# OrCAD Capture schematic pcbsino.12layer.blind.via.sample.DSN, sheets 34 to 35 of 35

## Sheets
34 Pg33: Expansion Connector: size C
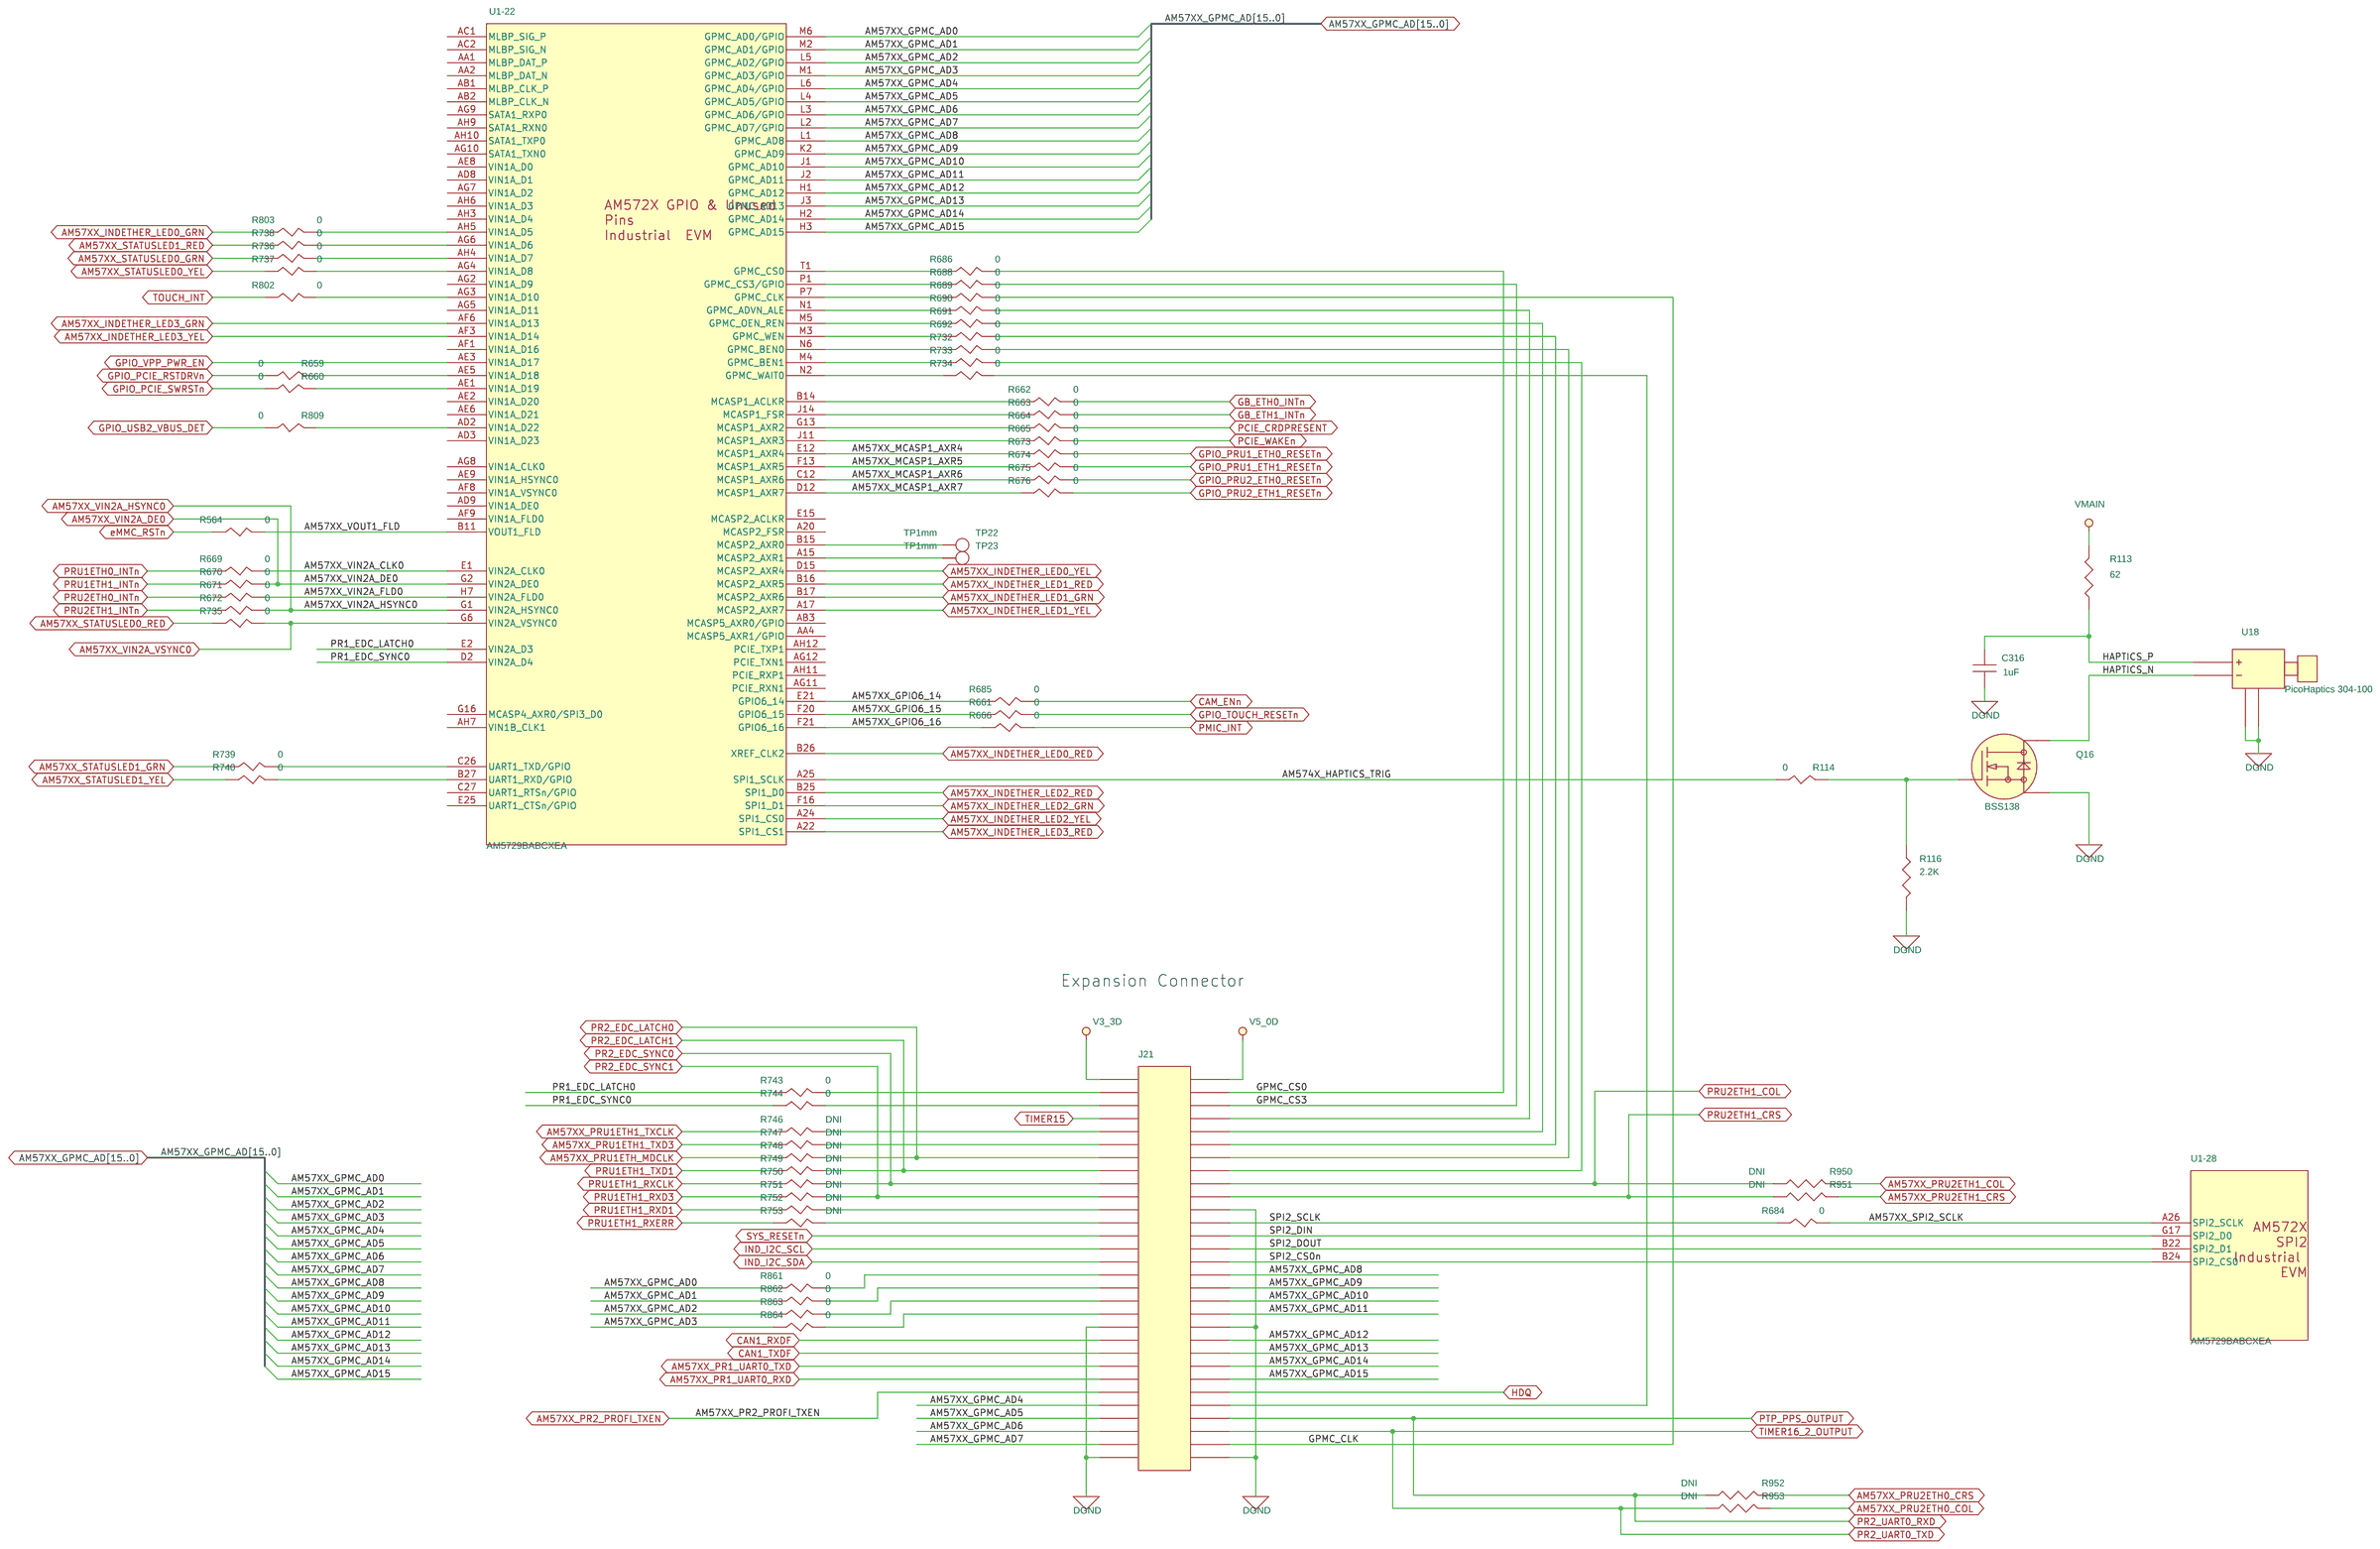
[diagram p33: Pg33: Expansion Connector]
35 Pg15: Ind Ethrnt & Status LED's: size C
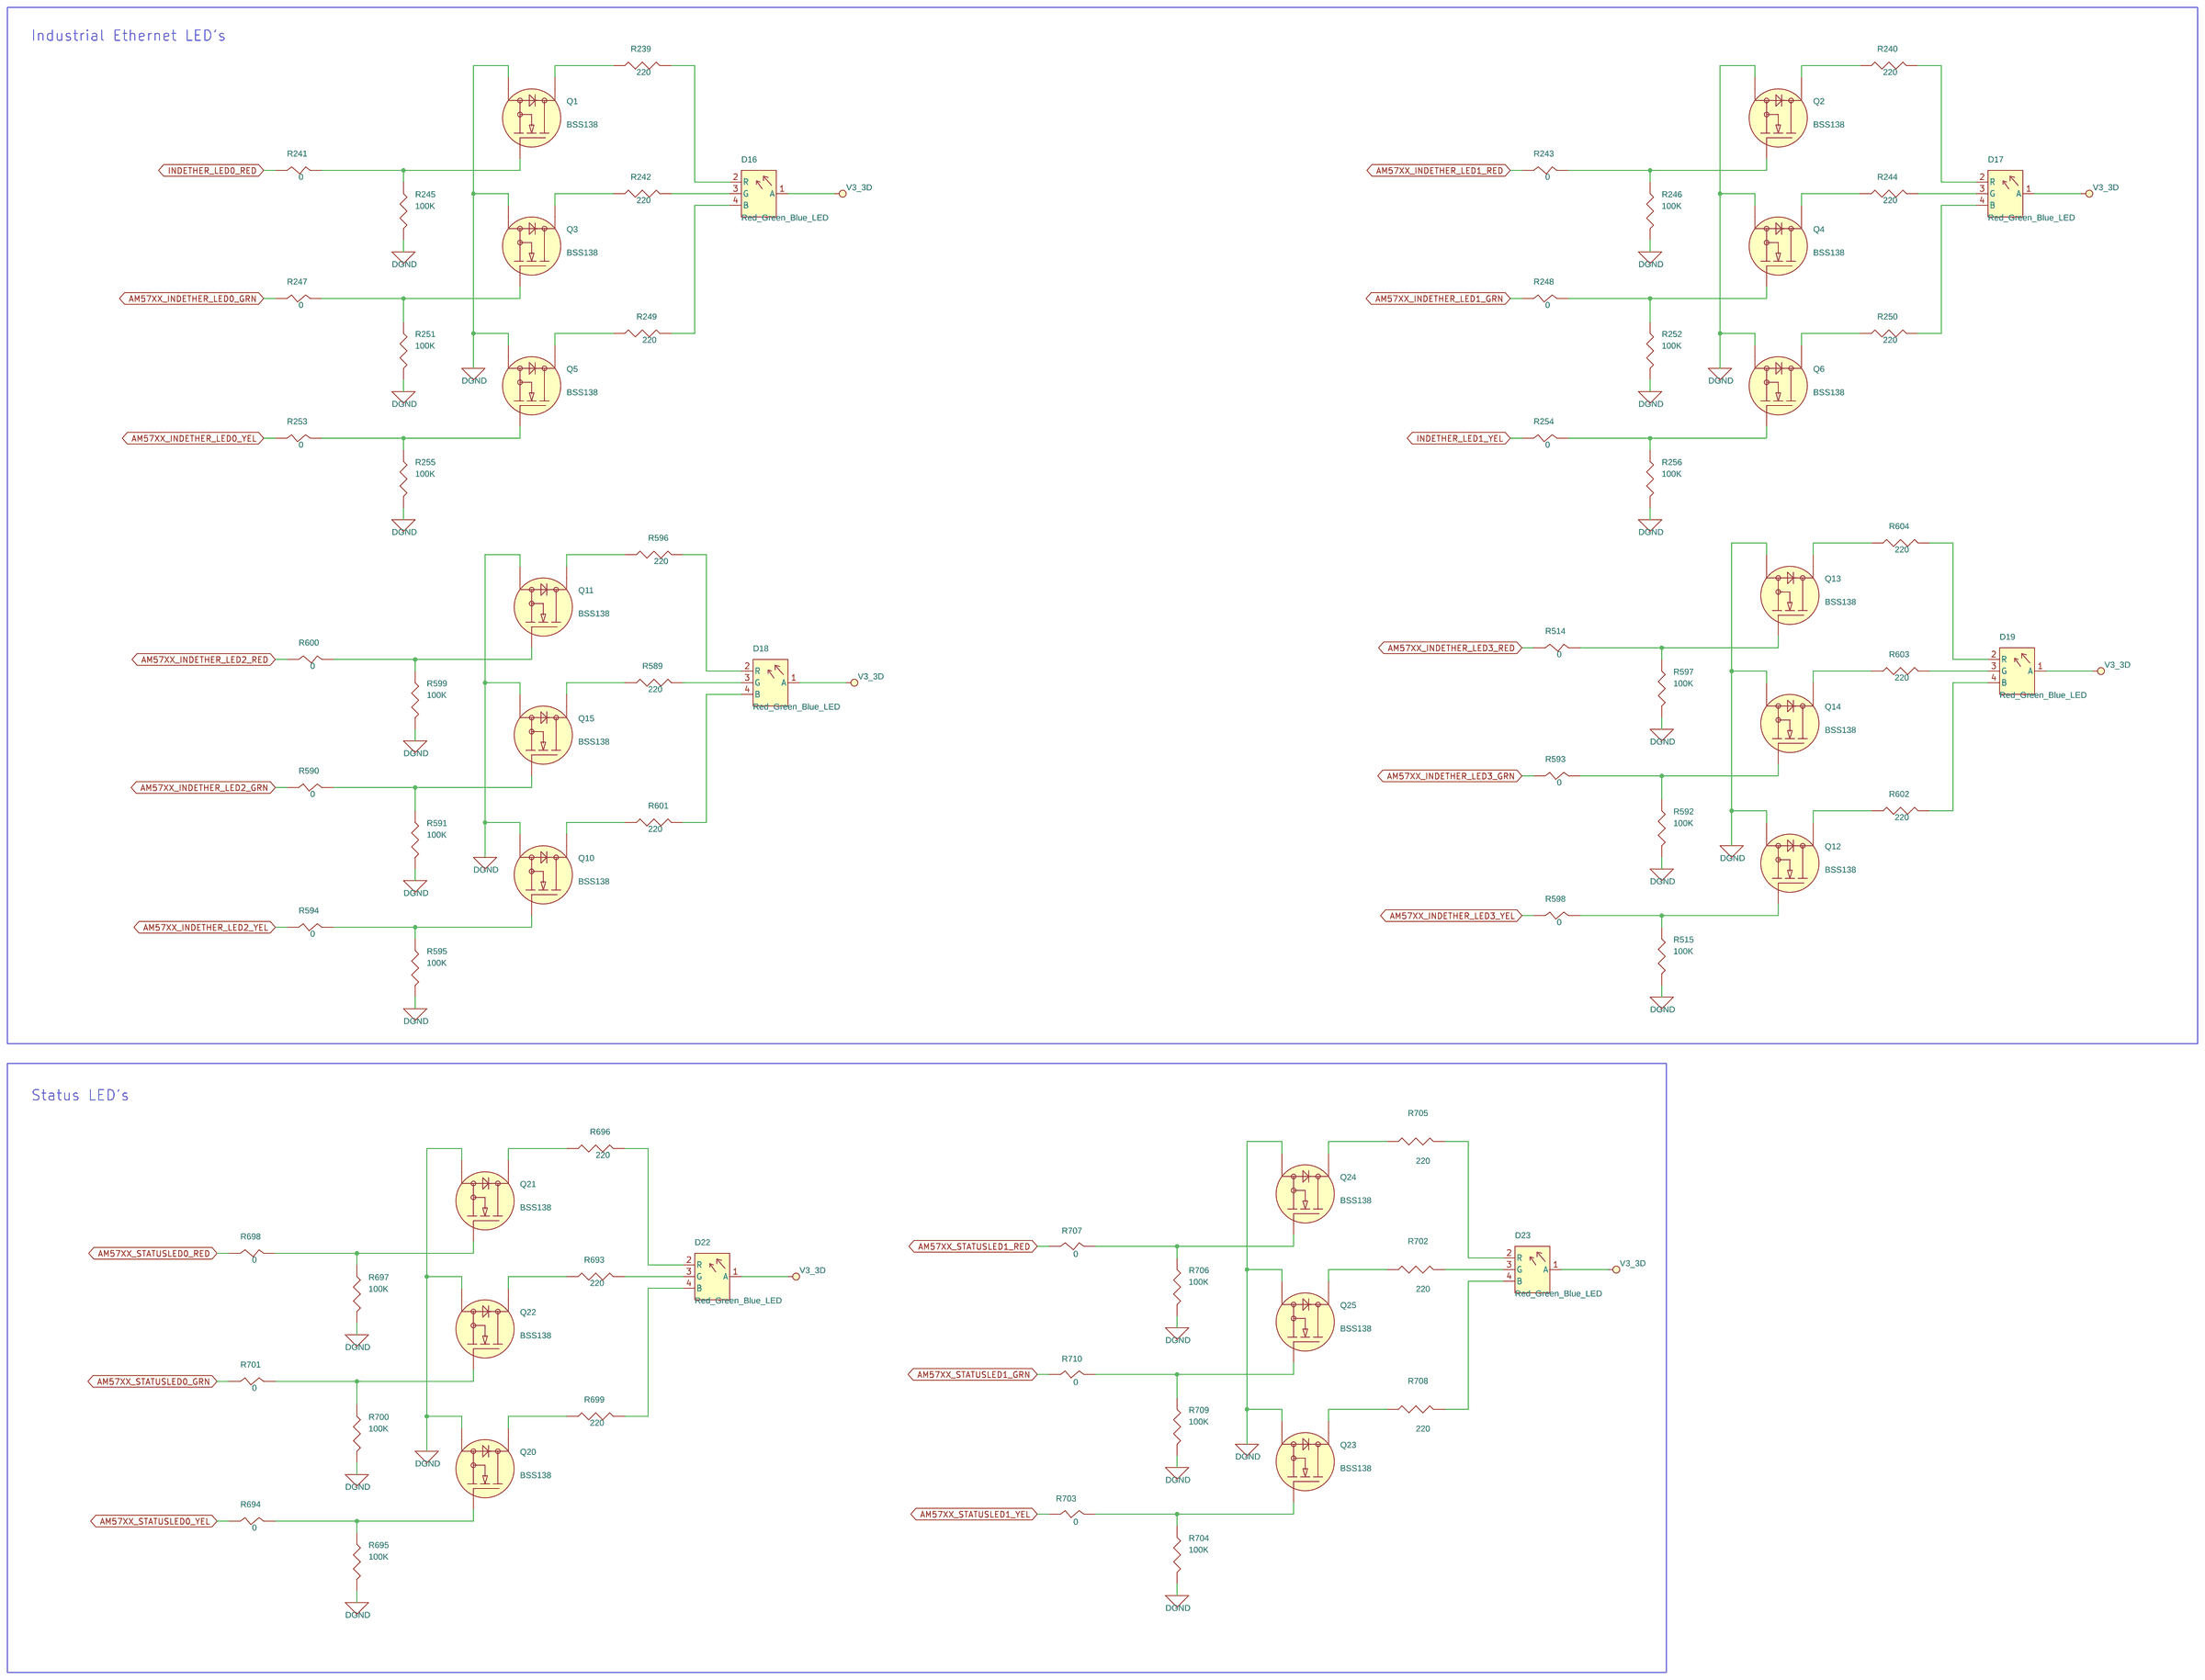
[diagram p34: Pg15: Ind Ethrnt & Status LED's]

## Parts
sheet Pg15: Ind Ethrnt & Status LED's
D16  Red_Green_Blue_LED  [LED-SM1210]
D17  Red_Green_Blue_LED  [LED-SM1210]
D18  Red_Green_Blue_LED  [LED-SM1210]
D19  Red_Green_Blue_LED  [LED-SM1210]
D22  Red_Green_Blue_LED  [LED-SM1210]
D23  Red_Green_Blue_LED  [LED-SM1210]
Q1  BSS138  [SOT23-3]
Q2  BSS138  [SOT23-3]
Q3  BSS138  [SOT23-3]
Q4  BSS138  [SOT23-3]
Q5  BSS138  [SOT23-3]
Q6  BSS138  [SOT23-3]
Q10  BSS138  [SOT23-3]
Q11  BSS138  [SOT23-3]
Q12  BSS138  [SOT23-3]
Q13  BSS138  [SOT23-3]
Q14  BSS138  [SOT23-3]
Q15  BSS138  [SOT23-3]
Q20  BSS138  [SOT23-3]
Q21  BSS138  [SOT23-3]
Q22  BSS138  [SOT23-3]
Q23  BSS138  [SOT23-3]
Q24  BSS138  [SOT23-3]
Q25  BSS138  [SOT23-3]
R239  220  [SM-7351-RES-0402]
R240  220  [SM-7351-RES-0402]
R241  0  [SM-7351-RES-0402]
R242  220  [SM-7351-RES-0402]
R243  0  [SM-7351-RES-0402]
R244  220  [SM-7351-RES-0402]
R245  100K  [SM-7351-RES-0402]
R246  100K  [SM-7351-RES-0402]
R247  0  [SM-7351-RES-0402]
R248  0  [SM-7351-RES-0402]
R249  220  [SM-7351-RES-0402]
R250  220  [SM-7351-RES-0402]
R251  100K  [SM-7351-RES-0402]
R252  100K  [SM-7351-RES-0402]
R253  0  [SM-7351-RES-0402]
R254  0  [SM-7351-RES-0402]
R255  100K  [SM-7351-RES-0402]
R256  100K  [SM-7351-RES-0402]
R514  0  [SM-7351-RES-0402]
R515  100K  [SM-7351-RES-0402]
R589  220  [SM-7351-RES-0402]
R590  0  [SM-7351-RES-0402]
R591  100K  [SM-7351-RES-0402]
R592  100K  [SM-7351-RES-0402]
R593  0  [SM-7351-RES-0402]
R594  0  [SM-7351-RES-0402]
R595  100K  [SM-7351-RES-0402]
R596  220  [SM-7351-RES-0402]
R597  100K  [SM-7351-RES-0402]
R598  0  [SM-7351-RES-0402]
R599  100K  [SM-7351-RES-0402]
R600  0  [SM-7351-RES-0402]
R601  220  [SM-7351-RES-0402]
R602  220  [SM-7351-RES-0402]
R603  220  [SM-7351-RES-0402]
R604  220  [SM-7351-RES-0402]
R693  220  [SM-7351-RES-0402]
R694  0  [SM-7351-RES-0402]
R695  100K  [SM-7351-RES-0402]
R696  220  [SM-7351-RES-0402]
R697  100K  [SM-7351-RES-0402]
R698  0  [SM-7351-RES-0402]
R699  220  [SM-7351-RES-0402]
R700  100K  [SM-7351-RES-0402]
R701  0  [SM-7351-RES-0402]
R702  220  [SM-7351-RES-0402]
R703  0  [SM-7351-RES-0402]
R704  100K  [SM-7351-RES-0402]
R705  220  [SM-7351-RES-0402]
R706  100K  [SM-7351-RES-0402]
R707  0  [SM-7351-RES-0402]
R708  220  [SM-7351-RES-0402]
R709  100K  [SM-7351-RES-0402]
R710  0  [SM-7351-RES-0402]
sheet Pg22: HDMI
U1  AM5729BABCXEA  [BGA23X23-760-117M]  (sections -1,-10,-11,-12,-13,-14,-15,-16,-17,-18,-19,-2,-20,-21,-22,-23,-24,-25,-26,-27,-28,-29,-3,-4,-5,-6,-7,-8,-9)
sheet Pg33: Expansion Connector
C316  1uF  [CC0603]
J21  Header_30x2_Female  [HDR2X30-2mm-177m]
Q16  BSS138  [SOT23-3]
R113  62  [sm-7351-res-0402]
R114  0  [SM-7351-RES-0402]
R116  2.2K  [sm-7351-res-0402]
R564  0  [SM-7351-RES-0402]
R659  0  [SM-7351-RES-0402]
R660  0  [SM-7351-RES-0402]
R661  0  [SM-7351-RES-0402]
R662  0  [SM-7351-RES-0402]
R663  0  [SM-7351-RES-0402]
R664  0  [SM-7351-RES-0402]
R665  0  [SM-7351-RES-0402]
R666  0  [SM-7351-RES-0402]
R669  0  [SM-7351-RES-0402]
R670  0  [SM-7351-RES-0402]
R671  0  [SM-7351-RES-0402]
R672  0  [SM-7351-RES-0402]
R673  0  [SM-7351-RES-0402]
R674  0  [SM-7351-RES-0402]
R675  0  [SM-7351-RES-0402]
R676  0  [SM-7351-RES-0402]
R684  0  [SM-7351-RES-0402]
R685  0  [SM-7351-RES-0402]
R686  0  [SM-7351-RES-0402]
R688  0  [SM-7351-RES-0402]
R689  0  [SM-7351-RES-0402]
R690  0  [SM-7351-RES-0402]
R691  0  [SM-7351-RES-0402]
R692  0  [SM-7351-RES-0402]
R732  0  [SM-7351-RES-0402]
R733  0  [SM-7351-RES-0402]
R734  0  [SM-7351-RES-0402]
R735  0  [SM-7351-RES-0402]
R736  0  [SM-7351-RES-0402]
R737  0  [SM-7351-RES-0402]
R738  0  [SM-7351-RES-0402]
R739  0  [SM-7351-RES-0402]
R740  0  [SM-7351-RES-0402]
R743  0  [SM-7351-RES-0402]
R744  0  [SM-7351-RES-0402]
R746  DNI  [SM-7351-RES-0402]
R747  DNI  [SM-7351-RES-0402]
R748  DNI  [SM-7351-RES-0402]
R749  DNI  [SM-7351-RES-0402]
R750  DNI  [SM-7351-RES-0402]
R751  DNI  [SM-7351-RES-0402]
R752  DNI  [SM-7351-RES-0402]
R753  DNI  [SM-7351-RES-0402]
R802  0  [SM-7351-RES-0402]
R803  0  [SM-7351-RES-0402]
R809  0  [SM-7351-RES-0402]
R861  0  [SM-7351-RES-0402]
R862  0  [SM-7351-RES-0402]
R863  0  [SM-7351-RES-0402]
R864  0  [SM-7351-RES-0402]
R950  DNI  [RC0402]
R951  DNI  [RC0402]
R952  DNI  [RC0402]
R953  DNI  [RC0402]
TP22  TP1mm  [tp_smd1mmcircle]
TP23  TP1mm  [tp_smd1mmcircle]
U18  PicoHaptics 304-100  [pico_304-100]

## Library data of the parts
D16-D19 D22 D23 = SM1210RGB: LED RedGreenBlue Tricolor 20mA  1210 smd; MANUFACTURER: Bivar
Q1-Q6 Q10-Q16 Q20-Q25 = 1Q_MOSFET_NChan_BSS138_0: MANUFACTURER: Diodes Inc.
R239 R240 R242 R244 R249 R250 R589 R596 R601-R604 R693 R696 R699 R702 R705 R708 = 1R_150ohm1_16W1%SMD0402: Resistor 220ohm 1/10W 1% 0402; MANUFACTURER: PANASONIC; MfrNum: ERJ-2RKF2200X; PartName: 220ohm1/10W1%0402; TIIntPartnumber: 1R0176
R114 R241 R243 R247 R248 R253 R254 R514 R564 R590 R593 R594 R598 R600 R659-R666 R669-R676 R684-R686 R688-R692 R694 R698 R701 R703 R707 R710 R732-R740 R743 R744 R746-R753 R802 R803 R809 R861-R864 = 1R_ZeroOhmResistor1_16W0402: Resistor Zero ohm Jumper 0402; MANUFACTURER: PANASONIC
R245 R246 R251 R252 R255 R256 R515 R591 R592 R595 R597 R599 R695 R697 R700 R704 R706 R709 = 1R_100KOhmResistor1_16W0402: Resistor 100Kohm 1/16W 1% 0402; MANUFACTURER: STACKPOLE ELECTRONICS
U1 = AM5729BABCXEA
C316 = CL10A105KB8NNNC
J21 = NPPN302AFCN-RC: Header, Socket, 30x2,  2mm pitch, Female; MANUFACTURER: Sullins
R113 = RMCF0402FT62R0
R116 = 1R_2.2KOhmResistor1_16W0402: MANUFACTURER: VishayDale
R950-R953 = ERJ-2GE0R00X
TP22 TP23 = 2H_Testpoint_SMD1mmCircle: Testpoint SMD 1mm circle pad; MANUFACTURER: N/A
U18 = 1G_Haptics_Pico_0: Haptics Vibrator 3V 15000 RPM; MANUFACTURER: PrecisionMicroDrive

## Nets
DGND: C316.2 J21.22 J21.39 J21.40 J21.59 J21.60 Q1.S(SOURCE) Q2.S(SOURCE) Q3.S(SOURCE) Q4.S(SOURCE) Q5.S(SOURCE) Q6.S(SOURCE) Q10.S(SOURCE) Q11.S(SOURCE) Q12.S(SOURCE) Q13.S(SOURCE) Q14.S(SOURCE) Q15.S(SOURCE) Q16.S(SOURCE) Q20.S(SOURCE) Q21.S(SOURCE) Q22.S(SOURCE) Q23.S(SOURCE) Q24.S(SOURCE) Q25.S(SOURCE) R116.1(P1) R245.1(P1) R246.1(P1) R251.1(P1) R252.1(P1) R255.1(P1) R256.1(P1) R515.1(P1) R591.1(P1) R592.1(P1) R595.1(P1) R597.1(P1) R599.1(P1) R695.1(P1) R697.1(P1) R700.1(P1) R704.1(P1) R706.1(P1) R709.1(P1) U18.M1 U18.M2 ; also on sheet 1 2 3 4 5 6 8 9 11 12 13 14 15 16 17 18 19 20 21 22 23 24 25 26 27 28 29 30 31 32 33
V3_3D: D16.1(A) D17.1(A) D18.1(A) D19.1(A) D22.1(A) D23.1(A) J21.1 ; also on sheet 2 3 4 5 6 8 9 11 12 13 14 15 16 17 18 19 21 22 23 24 25 26 27 28 29 30 31 32 33
V5_0D: J21.2 ; also on sheet 4 14 16 18 21
AM57XX_GPIO6_14: R685.2(P2) U1.E21(GPIO6_14)
AM57XX_GPIO6_15: R661.2(P2) U1.F20(GPIO6_15)
AM57XX_GPIO6_16: R666.2(P2) U1.F21(GPIO6_16)
AM57XX_GPMC_AD0: R861.2(P2) U1.M6(GPMC_AD0/GPIO) ; also on sheet 15
AM57XX_GPMC_AD1: R862.2(P2) U1.M2(GPMC_AD1/GPIO) ; also on sheet 15
AM57XX_GPMC_AD2: R863.2(P2) U1.L5(GPMC_AD2/GPIO) ; also on sheet 15
AM57XX_GPMC_AD3: R864.2(P2) U1.M1(GPMC_AD3/GPIO) ; also on sheet 15
AM57XX_GPMC_AD4: J21.51 U1.L6(GPMC_AD4/GPIO) ; also on sheet 15
AM57XX_GPMC_AD5: J21.53 U1.L4(GPMC_AD5/GPIO) ; also on sheet 15
AM57XX_GPMC_AD6: J21.55 U1.L3(GPMC_AD6/GPIO) ; also on sheet 15
AM57XX_GPMC_AD7: J21.57 U1.L2(GPMC_AD7/GPIO) ; also on sheet 15
AM57XX_GPMC_AD8: J21.32 U1.L1(GPMC_AD8) ; also on sheet 15
AM57XX_GPMC_AD9: J21.34 U1.K2(GPMC_AD9) ; also on sheet 15
AM57XX_GPMC_AD10: J21.36 U1.J1(GPMC_AD10) ; also on sheet 15
AM57XX_GPMC_AD11: J21.38 U1.J2(GPMC_AD11) ; also on sheet 15
AM57XX_GPMC_AD12: J21.42 U1.H1(GPMC_AD12) ; also on sheet 15
AM57XX_GPMC_AD13: J21.44 U1.J3(GPMC_AD13) ; also on sheet 15
AM57XX_GPMC_AD14: J21.46 U1.H2(GPMC_AD14) ; also on sheet 15
AM57XX_GPMC_AD15: J21.48 U1.H3(GPMC_AD15) ; also on sheet 15
AM57XX_INDETHER_LED0_GRN: R247.1(P1) R803.2(P2)
AM57XX_INDETHER_LED0_RED: U1.B26(XREF_CLK2) ; also on sheet 11
AM57XX_INDETHER_LED0_YEL: R253.1(P1) U1.D15(MCASP2_AXR4) ; also on sheet 11
AM57XX_INDETHER_LED1_GRN: R248.1(P1) U1.B17(MCASP2_AXR6)
AM57XX_INDETHER_LED1_RED: R243.2(P2) U1.B16(MCASP2_AXR5) ; also on sheet 11
AM57XX_INDETHER_LED1_YEL: U1.A17(MCASP2_AXR7) ; also on sheet 11
AM57XX_INDETHER_LED2_GRN: R590.1(P1) U1.F16(SPI1_D1)
AM57XX_INDETHER_LED2_RED: R600.2(P2) U1.B25(SPI1_D0)
AM57XX_INDETHER_LED2_YEL: R594.1(P1) U1.A24(SPI1_CS0)
AM57XX_INDETHER_LED3_GRN: R593.1(P1) U1.AF6(VIN1A_D13)
AM57XX_INDETHER_LED3_RED: R514.2(P2) U1.A22(SPI1_CS1)
AM57XX_INDETHER_LED3_YEL: R598.1(P1) U1.AF3(VIN1A_D14)
AM57XX_MCASP1_AXR4: R673.2(P2) U1.E12(MCASP1_AXR4)
AM57XX_MCASP1_AXR5: R674.2(P2) U1.F13(MCASP1_AXR5)
AM57XX_MCASP1_AXR6: R675.2(P2) U1.C12(MCASP1_AXR6)
AM57XX_MCASP1_AXR7: R676.2(P2) U1.D12(MCASP1_AXR7)
AM57XX_PR1_UART0_RXD: J21.47 ; also on sheet 12
AM57XX_PR1_UART0_TXD: J21.45 ; also on sheet 12 27
AM57XX_PR2_PROFI_TXEN: J21.49 ; also on sheet 12
AM57XX_PRU1ETH1_TXCLK: R746.2(P2) ; also on sheet 17
AM57XX_PRU1ETH1_TXD3: R747.2(P2) ; also on sheet 17
AM57XX_PRU1ETH_MDCLK: R748.2(P2) ; also on sheet 17 24
AM57XX_PRU2ETH0_COL: R953.1 ; also on sheet 27
AM57XX_PRU2ETH0_CRS: R952.1 ; also on sheet 27
AM57XX_PRU2ETH1_COL: R950.1 ; also on sheet 26
AM57XX_PRU2ETH1_CRS: R951.1 ; also on sheet 26
AM57XX_SPI2_SCLK: R684.1(P1) U1.A26(SPI2_SCLK)
AM57XX_STATUSLED0_GRN: R701.1(P1) R736.2(P2)
AM57XX_STATUSLED0_RED: R698.2(P2) R735.2(P2)
AM57XX_STATUSLED0_YEL: R694.1(P1) R737.2(P2)
AM57XX_STATUSLED1_GRN: R710.1(P1) R739.2(P2)
AM57XX_STATUSLED1_RED: R707.2(P2) R738.2(P2)
AM57XX_STATUSLED1_YEL: R703.1(P1) R740.2(P2)
AM57XX_VIN2A_CLK0: R669.1(P1) U1.E1(VIN2A_CLK0)
AM57XX_VIN2A_DE0: R670.1(P1) U1.G2(VIN2A_DE0) ; also on sheet 26
AM57XX_VIN2A_FLD0: R671.1(P1) U1.H7(VIN2A_FLD0)
AM57XX_VIN2A_HSYNC0: R672.1(P1) U1.G1(VIN2A_HSYNC0) ; also on sheet 26
AM57XX_VIN2A_VSYNC0: R735.1(P1) U1.G6(VIN2A_VSYNC0) ; also on sheet 27
AM57XX_VOUT1_FLD: R564.1(P1) U1.B11(VOUT1_FLD)
AM574X_HAPTICS_TRIG: R114.1(P1) U1.A25(SPI1_SCLK)
CAM_ENn: R685.1(P1) ; also on sheet 13
CAN1_RXDF: J21.41 ; also on sheet 8
CAN1_TXDF: J21.43 ; also on sheet 8
eMMC_RSTn: R564.2(P2) ; also on sheet 6
GB_ETH0_INTn: R662.1(P1) ; also on sheet 28
GB_ETH1_INTn: R663.1(P1) ; also on sheet 25
GPIO_PCIE_RSTDRVn: R659.1(P1) ; also on sheet 23
GPIO_PCIE_SWRSTn: R660.1(P1) ; also on sheet 23
GPIO_PRU1_ETH0_RESETn: R673.1(P1) ; also on sheet 24
GPIO_PRU1_ETH1_RESETn: R674.1(P1) ; also on sheet 17
GPIO_PRU2_ETH0_RESETn: R675.1(P1) ; also on sheet 27
GPIO_PRU2_ETH1_RESETn: R676.1(P1) ; also on sheet 26
GPIO_TOUCH_RESETn: R661.1(P1) ; also on sheet 5
GPIO_USB2_VBUS_DET: R809.1(P1) ; also on sheet 19
GPIO_VPP_PWR_EN: U1.AE3(VIN1A_D17) ; also on sheet 22
GPMC_CLK: J21.58 R689.1(P1)
GPMC_CS0: J21.4 R686.1(P1)
GPMC_CS3: J21.6 R688.1(P1)
HAPTICS_N: Q16.D(DRAIN) U18.2(N-)
HAPTICS_P: C316.1 R113.1 U18.1(P+)
HDQ: J21.50 ; also on sheet 13
IND_I2C_SCL: J21.27 ; also on sheet 5 13 15 18 19 23 28
IND_I2C_SDA: J21.29 ; also on sheet 5 13 15 18 19 23 28
INDETHER_LED0_RED: R241.2(P2) ; also on sheet 11
INDETHER_LED1_YEL: R254.1(P1) ; also on sheet 11
PCIE_CRDPRESENT: R664.1(P1) ; also on sheet 23
PCIE_WAKEn: R665.1(P1) ; also on sheet 23
PMIC_INT: R666.1(P1) ; also on sheet 19
PR1_EDC_LATCH0: R743.2(P2) U1.E2(VIN2A_D3)
PR1_EDC_SYNC0: R744.2(P2) U1.D2(VIN2A_D4)
PR2_EDC_LATCH0: J21.13 R748.1(P1) ; also on sheet 5
PR2_EDC_LATCH1: J21.15 R749.1(P1) ; also on sheet 5
PR2_EDC_SYNC0: J21.17 R750.1(P1) ; also on sheet 5 11
PR2_EDC_SYNC1: J21.19 R751.1(P1) ; also on sheet 5
PR2_UART0_RXD: J21.54 R952.2 ; also on sheet 5 11
PR2_UART0_TXD: J21.56 R953.2 ; also on sheet 5 11
PRU1ETH0_INTn: R669.2(P2) ; also on sheet 24
PRU1ETH1_INTn: R670.2(P2) ; also on sheet 17
PRU1ETH1_RXCLK: R750.2(P2) ; also on sheet 17
PRU1ETH1_RXD1: R752.2(P2) ; also on sheet 17
PRU1ETH1_RXD3: R751.2(P2) ; also on sheet 17
PRU1ETH1_RXERR: R753.2(P2) ; also on sheet 17
PRU1ETH1_TXD1: R749.2(P2) ; also on sheet 17
PRU2ETH0_INTn: R671.2(P2) ; also on sheet 27
PRU2ETH1_COL: J21.18 R950.2 ; also on sheet 26
PRU2ETH1_CRS: J21.20 R951.2 ; also on sheet 26
PRU2ETH1_INTn: R672.2(P2) ; also on sheet 26
SPI2_CS0n: J21.30 U1.B24(SPI2_CS0)
SPI2_DIN: J21.26 U1.G17(SPI2_D0)
SPI2_DOUT: J21.28 U1.B22(SPI2_D1)
SPI2_SCLK: J21.24 R684.2(P2)
SYS_RESETn: J21.25 ; also on sheet 5 30 31
TIMER15: J21.7 ; also on sheet 11
TOUCH_INT: R802.2(P2) ; also on sheet 5
VMAIN: R113.2 ; also on sheet 5 11 13 19 21
N17120040: J21.3 R743.1(P1)
N17120055: J21.5 R744.1(P1)
N17120061: J21.9 R746.1(P1)
N17120072: J21.11 R747.1(P1)
N17120087: J21.21 R752.1(P1)
N17120090: J21.23 R753.1(P1)
N17731118: Q1.G(GATE) R241.1(P1) R245.2(P2)
N17731139: Q5.G(GATE) R253.2(P2) R255.2(P2)
N20631200: Q16.G(GATE) R114.2(P2) R116.2(P2)
N20721609: Q3.G(GATE) R247.2(P2) R251.2(P2)
N20721766: Q3.D(DRAIN) R242.1(P1)
N20721850: Q1.D(DRAIN) R239.1(P1)
N20722196: D16.3(G) R242.2(P2)
N20722199: Q5.D(DRAIN) R249.1(P1)
N20722204: D16.4(B) R249.2(P2)
N20722213: D16.2(R) R239.2(P2)
N20722605: Q2.G(GATE) R243.1(P1) R246.2(P2)
N20722618: Q6.G(GATE) R254.2(P2) R256.2(P2)
N20722739: Q4.G(GATE) R248.2(P2) R252.2(P2)
N20722773: Q4.D(DRAIN) R244.1(P1)
N20722790: Q2.D(DRAIN) R240.1(P1)
N20722809: D17.3(G) R244.2(P2)
N20722811: Q6.D(DRAIN) R250.1(P1)
N20722815: D17.4(B) R250.2(P2)
N20722821: D17.2(R) R240.2(P2)
N20723137: Q11.G(GATE) R599.2(P2) R600.1(P1)
N20723150: Q10.G(GATE) R594.2(P2) R595.2(P2)
N20723271: Q15.G(GATE) R590.2(P2) R591.2(P2)
N20723305: Q15.D(DRAIN) R589.1(P1)
N20723322: Q11.D(DRAIN) R596.1(P1)
N20723341: D18.3(G) R589.2(P2)
N20723343: Q10.D(DRAIN) R601.1(P1)
N20723347: D18.4(B) R601.2(P2)
N20723353: D18.2(R) R596.2(P2)
N20723697: Q13.G(GATE) R514.1(P1) R597.2(P2)
N20723710: Q12.G(GATE) R515.2(P2) R598.2(P2)
N20723831: Q14.G(GATE) R592.2(P2) R593.2(P2)
N20723865: Q14.D(DRAIN) R603.1(P1)
N20723882: Q13.D(DRAIN) R604.1(P1)
N20723901: D19.3(G) R603.2(P2)
N20723903: Q12.D(DRAIN) R602.1(P1)
N20723907: D19.4(B) R602.2(P2)
N20723913: D19.2(R) R604.2(P2)
N20729664: Q20.D(DRAIN) R699.1(P1)
N20729666: D22.4(B) R699.2(P2)
N20729672: D22.2(R) R696.2(P2)
N20729903: Q21.G(GATE) R697.2(P2) R698.1(P1)
N20729915: Q20.G(GATE) R694.2(P2) R695.2(P2)
N20730029: Q22.G(GATE) R700.2(P2) R701.2(P2)
N20730054: Q22.D(DRAIN) R693.1(P1)
N20730079: Q21.D(DRAIN) R696.1(P1)
N20730095: D22.3(G) R693.2(P2)
N20730773: Q23.D(DRAIN) R708.1(P1)
N20730775: D23.4(B) R708.2(P2)
N20730781: D23.2(R) R705.2(P2)
N20730789: Q24.G(GATE) R706.2(P2) R707.1(P1)
N20730805: Q23.G(GATE) R703.2(P2) R704.2(P2)
N20730910: Q25.G(GATE) R709.2(P2) R710.2(P2)
N20730936: Q25.D(DRAIN) R702.1(P1)
N20730961: Q24.D(DRAIN) R705.1(P1)
N20730985: D23.3(G) R702.2(P2)
N20825141: R690.2(P2) U1.N1(GPMC_ADVN_ALE)
N20825143: R691.2(P2) U1.M5(GPMC_OEN_REN)
N20825145: R692.2(P2) U1.M3(GPMC_WEN)
N20825147: R732.2(P2) U1.N6(GPMC_BEN0)
N20825149: R733.2(P2) U1.M4(GPMC_BEN1)
N20825151: R734.2(P2) U1.N2(GPMC_WAIT0)
N21013400: R662.2(P2) U1.B14(MCASP1_ACLKR)
N21013403: R663.2(P2) U1.J14(MCASP1_FSR)
N21013406: R664.2(P2) U1.G13(MCASP1_AXR2)
N21013409: R665.2(P2) U1.J11(MCASP1_AXR3)
N21036279: J21.8 R690.1(P1)
N21036281: J21.10 R691.1(P1)
N21036293: J21.12 R692.1(P1)
N21036295: J21.14 R732.1(P1)
N21036304: J21.16 R733.1(P1)
N21036390: R686.2(P2) U1.T1(GPMC_CS0)
N21036392: R688.2(P2) U1.P1(GPMC_CS3/GPIO)
N21036394: R689.2(P2) U1.P7(GPMC_CLK)
N21036619: J21.52 R734.1(P1)
N21180149: TP22.1 U1.B15(MCASP2_AXR0)
N21180152: TP23.1 U1.A15(MCASP2_AXR1)
N21877717: R659.2(P2) U1.AE5(VIN1A_D18)
N21877759: R660.2(P2) U1.AE1(VIN1A_D19)
N21905162: R802.1(P1) U1.AG3(VIN1A_D10)
N21905296: R803.1(P1) U1.AH5(VIN1A_D5)
N22373548: R809.2(P2) U1.AD2(VIN1A_D22)
N22427447: R739.1(P1) U1.C26(UART1_TXD/GPIO)
N22427459: R740.1(P1) U1.B27(UART1_RXD/GPIO)
N22729003: J21.31 R861.1(P1)
N22729012: J21.33 R862.1(P1)
N22729021: J21.35 R863.1(P1)
N22729030: J21.37 R864.1(P1)
N22729576: R738.1(P1) U1.AG6(VIN1A_D6)
N22730116: R737.1(P1) U1.AG4(VIN1A_D8)
N22730128: R736.1(P1) U1.AH4(VIN1A_D7)

Not connected (* = marked no-connect by the designer): U1 A20(MCASP2_FSR) AA1(MLBP_DAT_P) AA2(MLBP_DAT_N) AA4(MCASP5_AXR1/GPIO) AB1(MLBP_CLK_P) AB2(MLBP_CLK_N) AB3(MCASP5_AXR0/GPIO) AC1(MLBP_SIG_P) AC2(MLBP_SIG_N) AD3(VIN1A_D23) AD8(VIN1A_D1) AD9(VIN1A_DE0) AE2(VIN1A_D20) AE6(VIN1A_D21) AE8(VIN1A_D0) AE9(VIN1A_HSYNC0) AF1(VIN1A_D16) AF8(VIN1A_VSYNC0) AF9(VIN1A_FLD0) AG2(VIN1A_D9) AG5(VIN1A_D11) AG7(VIN1A_D2) AG8(VIN1A_CLK0) AG9(SATA1_RXP0) AG10(SATA1_TXN0) AG11(PCIE_RXN1) AG12(PCIE_TXN1) AH3(VIN1A_D4) AH6(VIN1A_D3) AH7(VIN1B_CLK1) AH9(SATA1_RXN0) AH10(SATA1_TXP0) AH11(PCIE_RXP1) AH12(PCIE_TXP1) C27(UART1_RTSn/GPIO) E15(MCASP2_ACLKR) E25(UART1_CTSn/GPIO) G16(MCASP4_AXR0/SPI3_D0)

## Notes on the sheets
sheet 34
- Expansion Connector
sheet 35
- Industrial Ethernet LED's
- Status LED's
